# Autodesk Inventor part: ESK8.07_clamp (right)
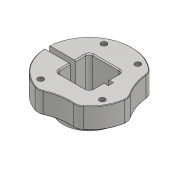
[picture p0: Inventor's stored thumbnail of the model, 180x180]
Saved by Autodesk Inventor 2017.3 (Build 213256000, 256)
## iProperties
Created: 2018-01
Part Number: ESK8.07_clamp (right)
Material: Aluminum 6061
Document SubType Name: Modeling
Designer: Tobias
Density: 2.7 g/cm^3
Appearance: Aluminum - Flat
Mass: 47.2154 g
Surface Area: 77.5268 cm^2
Volume: 17.4872 cm^3
Author: Tobias
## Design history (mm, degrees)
sketch "Sketch1"
  geometry: C1 r 24.5 at (0, 0); 1 further point
  constraints: 1 centre point, 1 coincident
  dimensions: "d0" = 49 diameter of C1
extrude "Extrusion1" new body sketch "Sketch1" stored distance "d1" = 12; taper "d2" = 0 deg
sketch "Sketch57"
  geometry: L1 (0, 34.3)-(0, -34.3) reference; L2 (-34.3, 0)-(34.3, 0) reference; L3 (-9.624, 18.1)-(0, 0); L4 (0, 0)-(10.25, 17.754); L5 (0, 0)-(-10.25, -17.754); L6 (0, 0)-(17.754, -10.25); A1 r 20.5 centre (0, 0) between (-9.624, 18.1) and (10.25, 17.754); 3 further points
  constraints: 8 end point, 4 coincident, 4 point on circle, 1 centre point
  dimensions: "d393" = 28 deg angle of L3 L1; "d394" = 41 diameter of A1; "d462" = 30 deg angle of L1 L4; "d512" = 30 deg angle of L1 L5; "d513" = 60 deg angle of L6 L1; "d552" = 30 deg angle of L2 L6 (derived)
hole "Hole13" sketch "Sketch57" at (-9.624, 18.1), (10.25, 17.754), (17.754, -10.25), (-10.25, -17.754) diameter "d395" = 3.242; stored, may be unused: countersink angle "d399" = 90 deg, drill point angle "d401" = 118 deg; dims "d396" = 8, "d397" = 4, "d398" = 2, "d400" = 11.8
workplane "Work Plane5"
workplane "Work Plane6"
workplane "Work Plane7"
sketch "Sketch68"
  geometry: L1 (12.95, 0)-(-12.95, 0) reference; L2 (0, 22.2)-(0, -3.7) reference; 2 further points
  constraints: 1 point on line
  dimensions: "d476" = 18.5 distance from line of point (0, 18.5) L1
hole "Hole15" sketch "Sketch68" at (0, 18.5) diameter "d464" = 5.5; stored, may be unused: countersink angle "d468" = 90 deg, drill point angle "d470" = 0 deg; dims "d465" = 6, "d466" = 10, "d467" = 17.75, "d469" = 57.25
sketch "Sketch71"
  geometry: L1 (6.51, 0)-(-6.51, 0) reference; L2 (0, 47.704)-(0, -7.951) reference; L3 (0, 18.5)-(0, 35.103); L4 (4.65, 18.5)-(4.65, 35.103); L5 (-4.65, 35.103)-(-4.65, 18.5); A1 r 4.65 centre (0, 18.5) between (-4.65, 18.5) and (4.65, 18.5); A2 r 4.65 centre (0, 35.103) between (4.65, 35.103) and (-4.65, 35.103); 2 further points
  constraints: 8 end point, 4 point on circle, 4 tangent, 2 centre point, 2 point on line, 1 midpoint, 1 parallel
  dimensions: "d477" = 9.3 distance between parallel lines of L5 L4; "d478" = 18.5 distance from line of L1 L3.start (derived)
extrude "Extrusion47" cut sketch "Sketch71" distance "d479" = 18; taper "d480" = 0 deg
sketch "Sketch72"
  geometry: L1 (0, -12.95)-(0, 12.95) reference; L2 (-3.7, 0)-(22.2, 0) reference; 2 further points
  constraints: 1 point on line
  dimensions: "d483" = 18.5 distance from line of point (18.5, 0) L1 (derived)
hole "Hole16" sketch "Sketch72" at (18.5, 0) diameter "d484" = 4.134; stored, may be unused: countersink angle "d488" = 90 deg, drill point angle "d490" = 118 deg; dims "d485" = 10, "d486" = 4, "d487" = 2, "d489" = 14.2
sketch "Sketch77"
  geometry: C1 r 15 at (0, 0); 1 further point
  constraints: 1 centre point, 1 coincident
  dimensions: "d527" = 30 diameter of C1
extrude "Extrusion52" join sketch "Sketch77" distance "d528" = 7; taper "d529" = 0 deg
sketch "Sketch78"
  geometry: L1 (-7.5, 9.5)-(7.5, 9.5); L2 (9.5, 7.5)-(9.5, -7.5); L3 (7.5, -9.5)-(-7.5, -9.5); L4 (-9.5, -7.5)-(-9.5, 7.5); L5 (0, 34.3)-(0, -34.3) reference; L6 (-34.3, 0)-(34.3, 0) reference; A1 r 2 centre (-7.5, -7.5) between (-9.5, -7.5) and (-7.5, -9.5); A2 r 2 centre (-7.5, 7.5) between (-7.5, 9.5) and (-9.5, 7.5); A3 r 2 centre (7.5, 7.5) between (9.5, 7.5) and (7.5, 9.5); A4 r 2 centre (7.5, -7.5) between (7.5, -9.5) and (9.5, -7.5); 5 further points
  constraints: 8 end point, 8 point on circle, 8 point on line, 8 tangent, 4 centre point, 3 equal radius, 2 parallel, 2 perpendicular, 1 horizontal, 2 other
  dimensions: "d532" = 19 distance of point (-9.5, -9.5) point (-9.5, 9.5); "d545" = 2 radius of A1 (derived)
extrude "Extrusion53" cut sketch "Sketch78" distance "d530" = 63; taper "d531" = 0 deg
sketch "Sketch66"
  geometry: L1 (20.363, 0)-(-34.675, 0) reference; L2 (-26.813, -1.5)-(-26.813, 1.5); L3 (-26.813, 1.5)-(12.5, 1.5); L4 (12.5, 1.5)-(12.5, -1.5); L5 (12.5, -1.5)-(-26.813, -1.5); L6 (0, 2.1)-(0, -2.1) reference
  constraints: 8 end point, 2 parallel, 1 perpendicular, 1 other
  dimensions: "d452" = 3 distance of L2.start L2.end; "d551" = 12.5 distance between parallel lines of L4 L6
extrude "Extrusion43" cut sketch "Sketch66" stored distance "d450" = 60; taper "d451" = 0 deg
chamfer "Chamfer44" distance "d542" = 0.6; stored, may be unused: second distance "d543" = 2, angle "d544" = 45 deg
workplane "Work Plane8"
sketch "Sketch76"
  geometry: L1 (0, -39.291)-(0, 64.247) reference; L2 (-101.901, 0)-(45.567, 0) reference; L3 (0, 0)-(-49.334, 17.956); C1 r 31.5 at (-49.334, 17.956)
  constraints: 2 end point, 1 centre point
  dimensions: "d520" = 63 diameter of C1; "d521" = 52.5 distance of L3.start L3.end; "d522" = 20 deg angle of L2 L3
extrude "Extrusion51" cut sketch "Sketch76" stored distance "d514" = 7.75; taper "d515" = 0 deg
mirror "Mirror11"
fillet "Fillet51" dims "d516" = 6
chamfer "Chamfer45" distance "d555" = 0.3; stored, may be unused: second distance "d556" = 2, angle "d557" = 45 deg
body "Solid1"
other parameters: "d71" = 6, "d72" = 16, "d405" = 0, "d449" = -90 deg, "d463" = -25.5, "d553" = 150 deg
